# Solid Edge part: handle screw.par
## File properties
Title: Handle Screw
Author: Robert a Rhodes jr
Template: Normal.par
Last saved by: CADCIM
Revision: 8
Application: Solid Edge
Material: aluminum
Accuracy: 0.99
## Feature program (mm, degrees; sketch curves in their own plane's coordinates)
sketch for "unnamed Protrusion 1" plane through (0, 0, 0) normal (0, -1, 0) x-axis (1, 0, 0)
  circle centre (0, 0) radius 7.5
extrude "unnamed Protrusion 1" add finite 14 along +normal
sketch for "Hole_1" plane through (0, -14, 0) normal (0, -1, 0) x-axis (1, 0, 0)
  hole centre (0, 0) bore radius 4
hole "Hole_1" diameter 8 finite  VBottomAngle = 120 deg
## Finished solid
Body 1: solid body, 5 faces, 4 edges, 1 vertex.
  Faces by surface: cylinder 2, plane 2, cone 1
  Edges by curve: circle 4
Bounding box of the edges (mm): 15.000 x 14.000 x 15.000, from (-7.5, -14, -7.5) to (7.5, 0, 7.5).
Cylindrical faces by radius (mm): R4 x1, R7.5 x1
Conical faces (half-angle, radius in mm at the cone's reference point): 60 deg R4 x1
Planar faces by outward normal: +y 1, -y 1
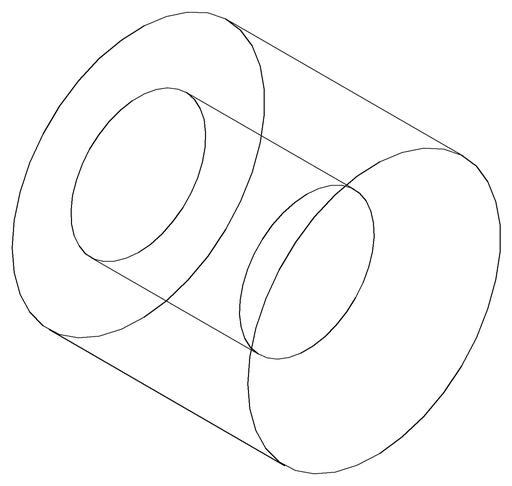
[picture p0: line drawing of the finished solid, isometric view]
